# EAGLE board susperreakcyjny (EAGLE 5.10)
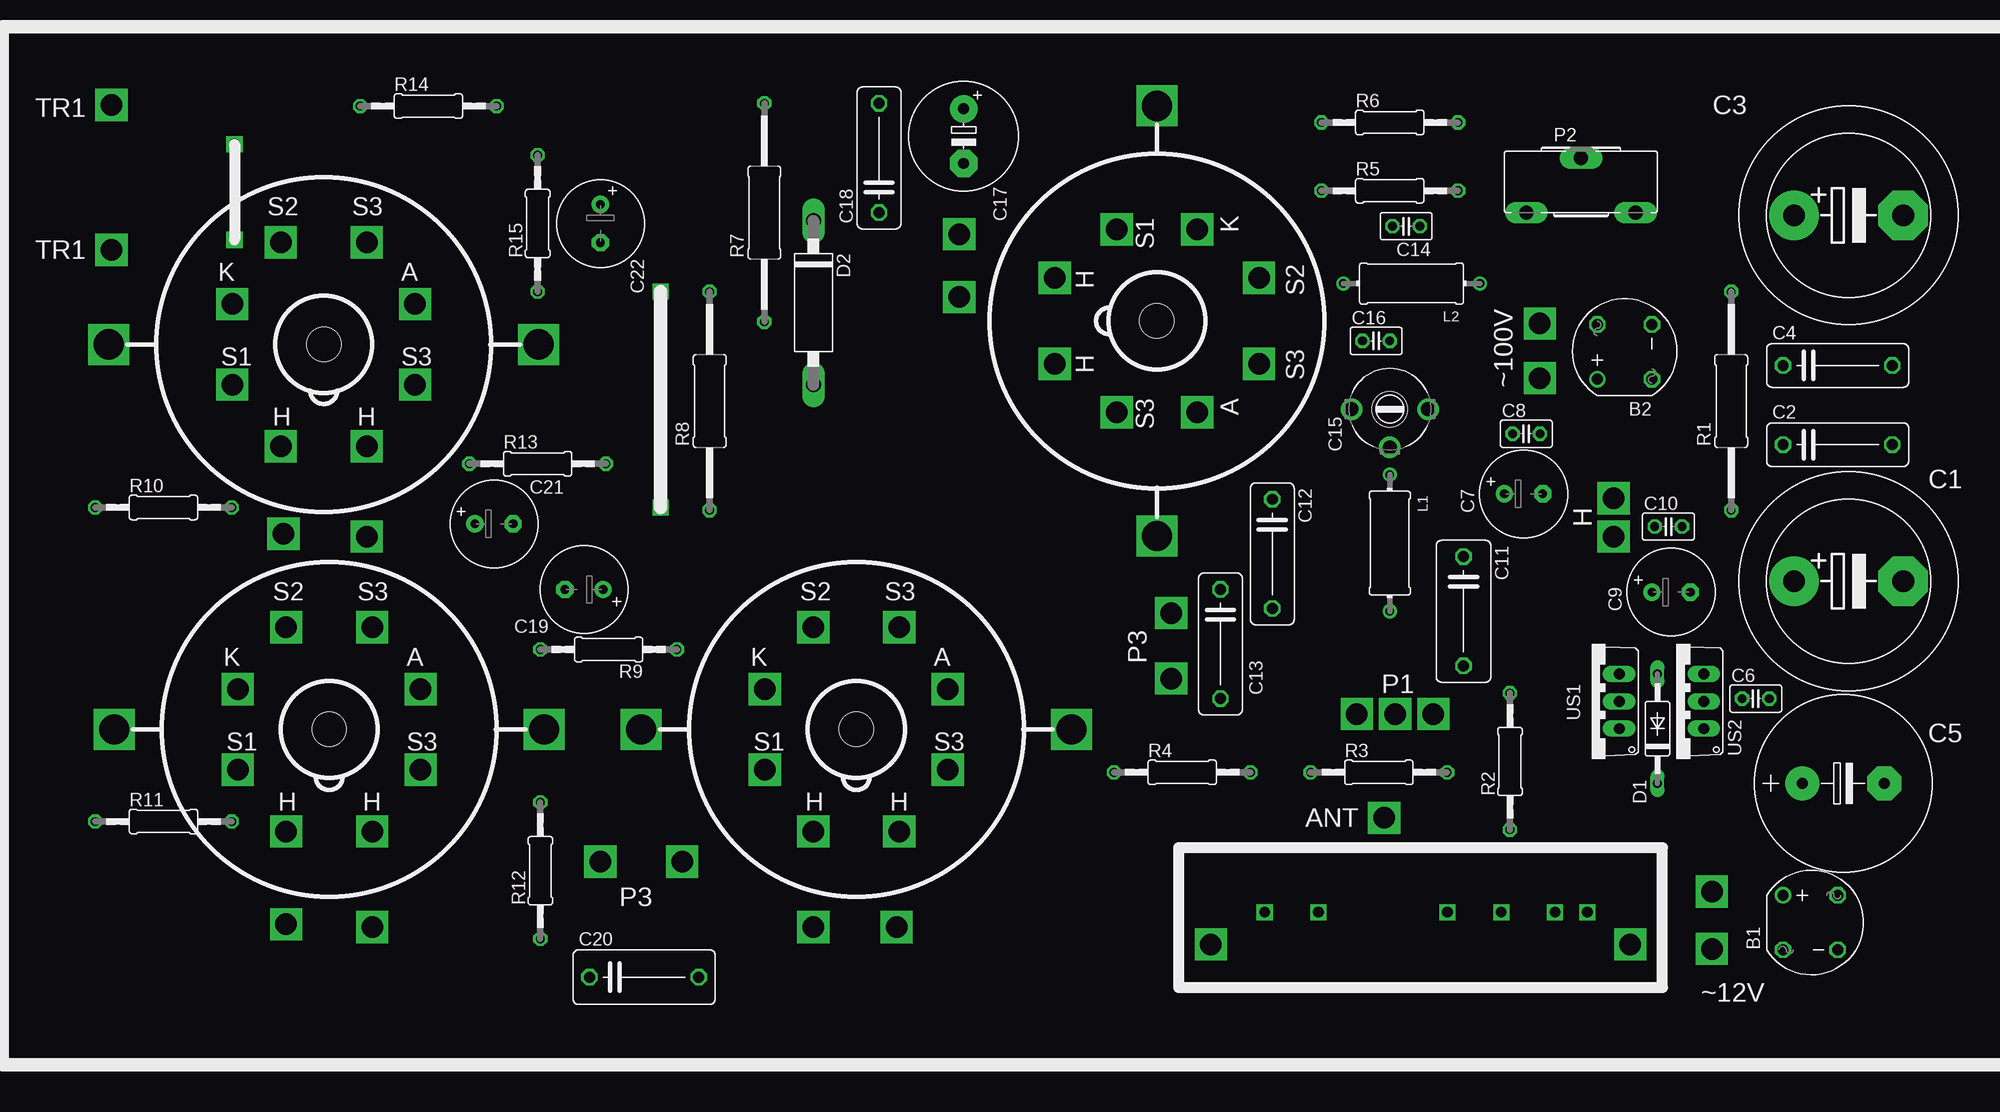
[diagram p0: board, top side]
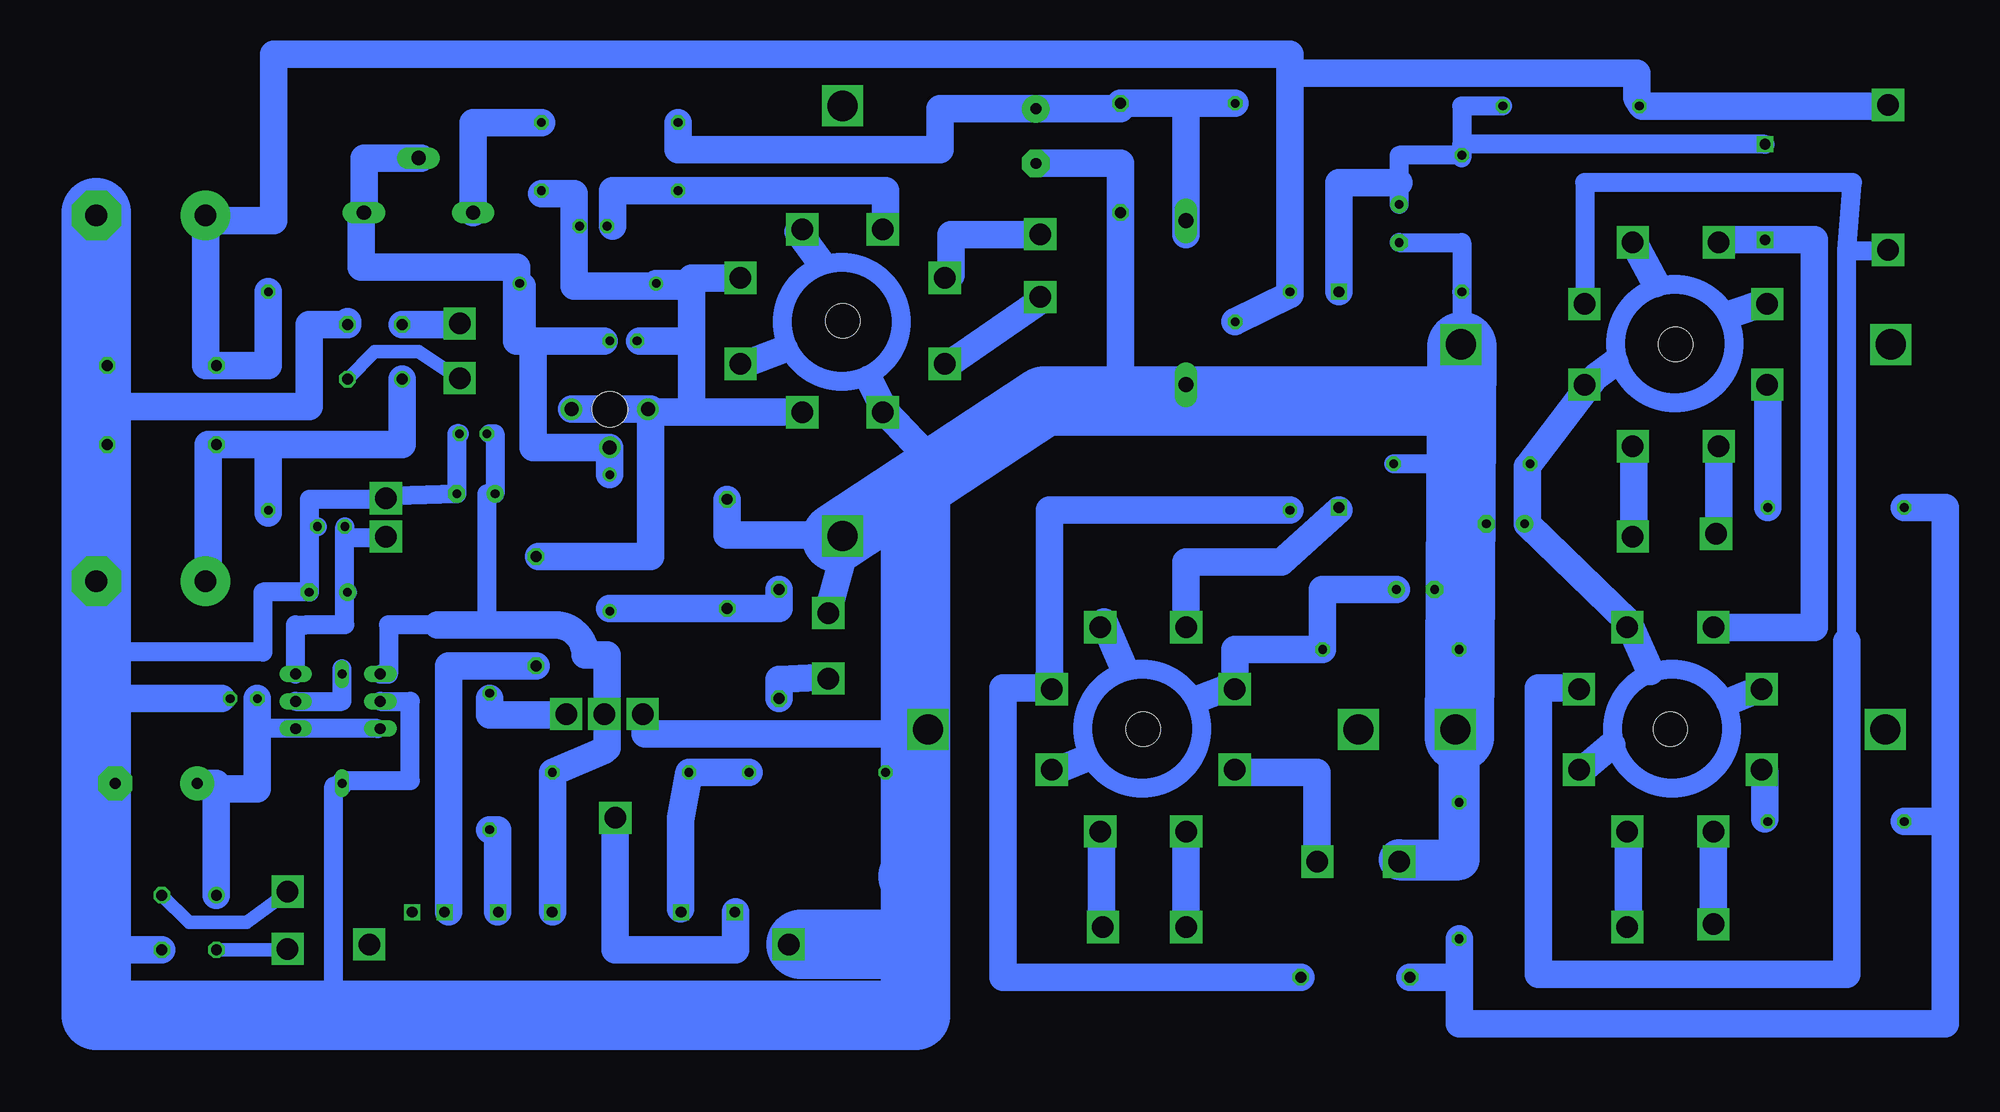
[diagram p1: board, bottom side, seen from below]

No outline drawn. Coordinates in mm, seen from the top.
Copper layers (1*16): Top 0.035mm / dielectric 1.5mm / Bottom 0.035mm
Design rules "default": minimum track width 10mil, minimum drill 24mil, track to track 8mil, track to pad 8mil, pad to pad 8mil, via to via 8mil, smd to smd 8mil, copper to edge 40mil, drill to drill 8mil, minimum pad ring 10mil, minimum via ring 8mil, stop-mask expansion 4mil, vias tented up to drill 0mil, thermal gap 10mil
Holes 3.2 mm at 30.4,30.92 107.37,68.92 29.89,66.73 79.42,30.92

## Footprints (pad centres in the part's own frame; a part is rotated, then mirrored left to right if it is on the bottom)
RB1A = drill 1.016 round: + -2.54,2.54 | drill 1.016 octagon: - 2.54,-2.54; AC1 2.54,2.54; AC2 -2.54,-2.54
EB20D = drill 2.007 pad 4.597 round: + -5.08,0 | drill 2.007 pad 4.597 octagon: - 5.08,0
C102-043X133 = drill 1.016 octagon: 1 -5.08,0; 2 5.08,0
E7,5-16 = drill 1.016 pad 3.15 round: + -3.81,0 | drill 1.016 pad 3.15 octagon: - 3.81,0
C025-025X050 = drill 0.813 octagon: 1 -1.27,0; 2 1.27,0
E3,5-8 = drill 0.813 pad 1.6 round: + -1.778,0 | drill 0.813 pad 1.6 octagon: - 1.778,0
C102-054X133 = drill 1.016 octagon: 1 -5.08,0; 2 5.08,0
CTRIM808-1 = drill 1.321 round: 1 -3.556,0; 2 0,-3.556; 3 3.556,0 | hole 3.302: 0,0
E5-10,5 = drill 1.016 pad 2.54 round: + -2.54,0 | drill 1.016 pad 2.54 octagon: - 2.54,0
C2992 = drill 0.813 long: A 5.08,0; C -5.08,0
C1702-15 = drill 1.397 long: A 7.62,0; C -7.62,0
LAL04 = drill 0.8 pad 1.3 round: 1 -6.35,0; 2 6.35,0
CA14H = drill 1.321 long: A -5.08,0; E 5.08,0; S 0,5.08
0309/20 = drill 0.813 octagon: 1 -10.16,0; 2 10.16,0
0207/12 = drill 0.813 octagon: 1 -6.35,0; 2 6.35,0
TO220V = drill 1.016 long: 1 -2.54,-2.54; 2 0,-2.54; 3 2.54,-2.54

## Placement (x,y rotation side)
B1  [RB1A]  168.15,12.95 0 top
B2  [RB1A]  150.88,66.04 90 top
C1  [EB20D]  171.7,44.7 0 top
C2  [C102-043X133]  170.69,57.4 0 top
C3  [EB20D]  171.7,78.74 0 top
C4  [C102-043X133]  170.69,64.77 0 top
C5  [E7,5-16]  171.2,25.91 0 top
C6  [C025-025X050]  163.07,33.78 0 top
C7  [E3,5-8]  141.48,52.83 0 top
C8  [C025-025X050]  141.73,58.42 0 top
C9  [E3,5-8]  155.19,43.69 0 top
C10  [C025-025X050]  154.94,49.78 0 top
C11  [C102-054X133]  135.89,41.91 270 top
C12  [C102-043X133]  118.11,47.24 270 top
C13  [C102-043X133]  113.28,38.86 270 top
C14  [C025-025X050]  130.56,77.72 180 top
C15  [CTRIM808-1]  129.03,60.71 0 top
C16  [C025-025X050]  127.76,67.06 0 top
C17  [E5-10,5]  89.41,86.11 270 top
C18  [C102-043X133]  81.53,84.07 90 top
C19  [E3,5-8]  54.1,43.94 180 top
C20  [C102-054X133]  59.69,7.87 0 top
C21  [E3,5-8]  45.72,50.04 0 top
C22  [E3,5-8]  55.63,77.98 270 top
D1  [C2992]  153.92,30.99 90 top
D2  [C1702-15]  75.44,70.61 270 top
L1  [LAL04]  129.03,48.26 270 top
L2  [LAL04]  131.06,72.39 180 top
P2  [CA14H]  146.81,78.99 0 top
R1  [0309/20]  160.78,61.47 90 top
R2  [0207/12]  140.21,27.94 90 top
R3  [0207/12]  128.02,26.92 0 top
R4  [0207/12]  109.73,26.92 0 top
R5  [0207/12]  129.03,81.03 0 top
R6  [0207/12]  129.03,87.38 0 top
R7  [0309/20]  70.87,78.99 90 top
R8  [0309/20]  65.79,61.47 90 top
R9  [0207/12]  56.39,38.35 180 top
R10  [0207/12]  14.99,51.56 0 top
R11  [0207/12]  14.99,22.35 0 top
R12  [0207/12]  50.04,17.78 90 top
R13  [0207/12]  49.78,55.63 0 top
R14  [0207/12]  39.62,88.9 0 top
R15  [0207/12]  49.78,77.98 90 top
US1  [TO220V]  147.83,33.53 90 top
US2  [TO220V]  155.7,33.53 90 top

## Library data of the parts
B1 B2 = rectifier
C1-C22 L1 L2 R1-R15 = rcl
D1 D2 = diode
P2 = pot
US1 US2 = transistor-npn

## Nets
S$37: C22.- R15.1
S$40: R10.2
S$41: C20.1 R10.1 R11.1 R12.1
S$43: R13.2
S$46: C22.+ R14.2
S$47: R12.2
S$62: C19.+ R9.1
S$63: C20.2 R8.1
S$69: C17.+ C18.2 R7.2
S$72: L2.2
S$74: P2.E
S$75: C17.-
S$76: C15.2 L1.1
S$77: C12.2
S$80: C13.2
S$81: C15.3
S$92: C11.2
S$94: R3.1 R4.2
S$95: R3.2
S$97: R2.1
S$99: C9.- C10.2
S$100: C13.1
S$101: B2.AC2
S$102: R1.2 R7.1
S$104: B2.+ C2.1
S$105: B2.AC1
S$106: D1.A
S$108: B1.AC1
S$109: B1.-
S$110: B1.+ C5.+
S$112: C6.1
S$114: US1.3
S$115: P2.A R6.2
S$116: C7.- C8.2
S$117: C7.+
S$119: US2.2
S$120: US1.2
S$121: C9.+ C10.1 US2.3
S$122: R6.1
S$129: C12.1

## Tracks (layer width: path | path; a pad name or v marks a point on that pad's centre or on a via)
S$1  (via drill 2)
  other vias: 34.4,40.41
S$2  (via drill 2)
  other vias: 26.4,40.41
S$3  (via drill 2)
  other vias: 21.9,34.67
S$4  (via drill 2)
  other vias: 38.9,34.67
S$5  (via drill 2)
  other vias: 38.9,27.17
S$6  (via drill 2)
  other vias: 21.9,27.17
S$7  (via drill 2)
  other vias: 26.4,21.43 26.4,12.79 10.14,75.53 10.14,88.99
S$8  (via drill 2)
  other vias: 34.4,21.43 34.4,12.54
S$9  (via drill 2.8)
  other vias: 50.4,30.92
S$10  (via drill 2.8)
  other vias: 10.4,30.92
S$11  (via drill 2)
  other vias: 116.87,72.92
S$12  (via drill 2)
  other vias: 116.87,64.92
S$13  (via drill 2)
  other vias: 111.12,77.42
S$14  (via drill 2)
  other vias: 111.12,60.42
S$15  (via drill 2)
  other vias: 103.63,60.42
S$16  (via drill 2)
  other vias: 103.63,77.42
S$17  (via drill 2)
  other vias: 97.88,72.92 88.99,76.98 88.99,71.14
S$18  (via drill 2)
  other vias: 97.88,64.92
S$19  (via drill 2.8)
  other vias: 107.37,48.92
S$20  (via drill 2.8)
  other vias: 107.37,88.92
S$21  (via drill 2)
  other vias: 25.89,76.23
S$22  (via drill 2)
  other vias: 33.89,76.23
S$23  (via drill 2)
  other vias: 21.39,70.48
S$24  (via drill 2)
  other vias: 38.39,70.48
S$25  (via drill 2)
  other vias: 38.39,62.99
S$26  (via drill 2)
  other vias: 21.39,62.99
S$27  (via drill 2)
  other vias: 25.89,57.24 26.14,49.11
S$28  (via drill 2)
  other vias: 33.89,57.24 33.89,48.86
S$29  (via drill 2.8)
  other vias: 49.89,66.73
S$30  (via drill 2.8)
  other vias: 9.89,66.73
S$31
  Bottom 2.54: 37.34,63.75 35.56,65.02 | 37.34,63.75 38.35,62.74 | 37.34,63.75 43.69,55.37 43.69,50.04 34.29,40.89 32.26,36.32
S$32
  Bottom 2.54: 26.42,21.08 26.42,12.95
S$33
  Bottom 2.54: 34.29,20.83 34.29,12.45
S$34
  Bottom 2.54: 88.9,76.96 97.28,76.96 97.28,73.15
S$35
  Bottom 2.54: 25.91,56.39 25.91,49.02
S$36
  Bottom 2.54: 33.78,56.64 33.78,48.77
S$37
  Bottom 1.778: 49.78,66.55 R15.1 49.78,76.2 C22.-
  Bottom 6.452: 49.78,66.55 50.04,30.23
S$38  (via drill 1)
  Bottom 2.54: 25.91,76.45 v21.59,76.45 17.02,76.45 17.02,40.39 26.42,40.39
S$39
  Bottom 2.54: 21.59,22.61 21.59,26.92
S$40
  Bottom 2.54: R10.2 21.34,62.74
S$41
  Bottom 2.54: R10.1 4.83,51.56 4.83,22.35 | 4.83,22.35 R11.1 | 4.83,22.35 4.83,3.56 50.04,3.56 50.04,7.87 | R12.1 50.04,7.87 | C20.1 50.04,7.87
S$42
  Bottom 1.778: 38.35,70.61 38.35,81.79 13.46,81.79 13.97,75.44 | 13.97,75.44 10.16,75.44 | 13.97,39.62 13.97,75.44
S$43
  Bottom 1.778: R13.2 51.82,55.63 51.82,55.37
S$44
  Bottom 2.54: 174.5,60.96 156.97,60.96 156.97,68.58 153.42,68.58 153.42,68.83
S$45
  Bottom 2.54: 88.9,70.87 97.28,65.02
S$46  (via drill 1)
  Bottom 1.778: R14.2 49.78,88.9 49.78,85.34 | 49.78,84.33 49.78,84.07 | 49.78,84.33 55.63,84.33 55.63,81.79 C22.+ | v21.59,85.34 49.78,85.34 | 49.78,85.34 49.78,84.33
  Bottom 2.54: 55.63,81.79 61.21,81.79 v61.21,71.63
S$47
  Bottom 2.54: R12.2 50.04,28.45
S$48  (via drill 2)
  other vias: 75.42,40.41
S$49  (via drill 2)
  other vias: 83.42,40.41
S$50  (via drill 2)
  other vias: 70.92,34.67
S$51  (via drill 2)
  other vias: 87.92,34.67
S$52  (via drill 2)
  other vias: 87.92,27.17
S$53  (via drill 2)
  other vias: 70.92,27.17
S$54  (via drill 2)
  other vias: 75.42,21.43 75.42,12.54 63.23,18.63 55.61,18.63 108.69,35.65 108.69,41.75 128.51,22.7 133.08,32.35 129.52,32.35 125.97,32.35 142.98,68.67 142.98,63.59 158.99,10.51 158.99,15.84 149.84,52.42 149.84,48.86
S$55  (via drill 2)
  other vias: 83.42,21.43 83.17,12.54
S$56  (via drill 2.8)
  other vias: 99.42,30.92
S$57  (via drill 2.8)
  other vias: 59.42,30.92
S$58
  Bottom 3.81: 55.63,18.8 50.04,18.8 50.04,30.73
S$59
  Bottom 2.54: 87.88,26.92 84.84,28.19
S$60
  Bottom 2.54: 75.44,20.83 75.44,12.7
S$61
  Bottom 2.54: 83.31,20.83 83.31,12.7
S$62
  Bottom 2.54: C19.+ 62.74,43.94 R9.1 70.87,38.35 70.87,35.05 74.17,33.78
S$63
  Bottom 2.54: 87.88,34.8 88.14,34.8 | 88.14,34.8 92.46,34.8 92.46,7.87 C20.2 | R8.1 88.14,51.31 88.14,34.8
S$64  (via drill 1)
  other vias: 61.21,51.56
S$65
  Bottom 2.54: 99.06,55.88 103.38,60.45 104.9,63.5
S$66
  Bottom 2.54: 61.21,51.31 66.55,46.48 75.44,46.48 75.44,40.89
S$67
  Bottom 6.452: 50.04,61.47 88.65,61.47 107.95,48.77
S$68
  Bottom 2.54: 103.38,77.72 103.38,81.03 128.78,81.03 128.78,77.72
S$69
  Bottom 2.54: 98.3,84.84 98.3,88.65 C17.+ 81.53,88.65 C18.2 75.44,89.15 | 75.44,89.15 R7.2 | 75.44,76.96 75.44,89.15
S$70
  Bottom 2.54: 70.87,26.92 63.25,26.92 63.25,18.54
S$71
  Bottom 2.54: 126.24,67.06 121.67,67.06
S$72
  Bottom 2.54: 135.38,80.77 132.33,80.77 132.33,72.14 121.41,72.14 | 111.51,60.45 121.41,60.45 | 121.41,60.45 121.41,72.14 | 121.41,72.14 121.41,72.39 | 121.41,72.39 121.41,72.9 117.35,72.9 | L2.2 121.41,72.39 | 125.48,60.45 121.41,60.45
S$74
  Bottom 2.54: 146.56,84.07 151.89,84.07 P2.E 152.15,78.99 152.15,73.91 137.67,73.91 137.67,67.06
S$75
  Bottom 2.54: C17.- 81.53,83.57 81.53,62.74
S$76
  Bottom 2.54: L1.1 C15.2 136.14,57.15 136.14,66.8 136.14,67.06 | 137.16,72.14 137.16,67.06 136.14,67.06 | 129.54,67.06 136.14,67.06
S$77
  Bottom 2.54: 129.03,42.16 C12.2 113.28,42.16
S$78
  Bottom 6.452: 111.25,10.92 100.58,10.92 100.58,53.34
S$79
  Bottom 2.54: 108.71,41.91 106.68,49.28
S$80
  Bottom 2.54: 108.71,35.81 113.28,35.56 C13.2
S$81
  Bottom 2.54: 135.64,46.99 125.22,46.99 125.22,60.71 C15.3
S$82  (via drill 2)
  other vias: 112.4,10.92
S$83  (via drill 2)
  other vias: 151.4,10.92
S$84  (via drill 1)
  other vias: 147.4,13.92
S$85  (via drill 1)
  other vias: 144.4,13.92
S$86  (via drill 1)
  other vias: 139.4,13.92
S$87  (via drill 1)
  other vias: 134.4,13.92
S$88  (via drill 1)
  other vias: 122.4,13.92
S$89  (via drill 1)
  other vias: 117.4,13.92
S$90
  Bottom 3.81: 112.27,10.92 101.6,10.92 101.6,52.07
S$91
  Bottom 2.54: 117.35,13.97 117.35,10.41 128.52,10.41 128.52,22.61
S$92
  Bottom 2.54: 144.02,13.97 144.02,36.83 C11.2
S$93
  Bottom 6.452: 100.84,17.27 100.58,17.27 100.58,4.32 176.78,4.32 176.78,78.99
S$94
  Bottom 2.54: 122.43,14.22 122.43,22.61 R3.1 R4.2
S$95
  Bottom 2.54: 134.37,13.97 R3.2 129.54,28.96
S$96
  Bottom 2.54: 125.73,32.51 125.73,30.48 102.11,30.48
S$97
  Bottom 2.54: 139.45,13.97 139.45,21.59 R2.1
S$98
  Bottom 2.54: 140.21,33.78 140.21,32.26 133.35,32.26
S$99
  Bottom 1.778: C10.2 156.97,49.78 | 156.97,49.78 156.97,45.47 C9.- 161.29,43.69 161.29,38.1 175.01,38.1 | 150.11,52.32 156.97,52.32 156.97,49.78
S$100
  Bottom 2.54: C13.1 113.28,42.42
S$101
  Bottom 1.27: B2.AC2 150.88,66.04 146.81,66.04 143,63.5
S$102
  Bottom 1.778: 33.02,88.9 33.27,89.66
  Bottom 2.54: R1.2 160.78,64.77 166.62,64.77 166.62,78.23 160.27,78.23 160.27,93.73 65.79,93.73 65.79,91.95 | 10.16,88.9 33.02,88.9 33.53,89.66 33.53,91.95 65.79,91.95 | 65.79,91.95 65.79,71.37 R7.1
S$103
  Bottom 2.54: 174.75,60.45 174.75,60.71
S$104
  Bottom 2.54: B2.+ 148.34,57.4 160.78,57.4 | 166.37,44.7 166.37,57.4 C2.1 160.78,57.4 | 160.78,57.4 160.78,51.05
S$105
  Bottom 2.54: 143,68.58 B2.AC1
S$106
  Bottom 1.778: 153.92,33.78 D1.A
S$107
  Bottom 1.27: 165.35,10.41 159,10.41
S$108
  Bottom 1.27: B1.AC1 168.15,12.95 162.81,12.95 159,15.75
S$109
  Bottom 2.54: B1.- 174.5,10.41
S$110
  Bottom 2.54: B1.+ 165.61,25.91 C5.+
S$111
  Bottom 2.54: 165.1,33.78 174.5,33.78
S$112
  Bottom 2.54: C6.1 161.8,25.4 165.86,25.4
S$113
  Bottom 1.778: 147.57,33.53 147.57,26.16 153.92,26.16 153.92,25.65 154.69,25.65 154.69,4.06
S$114
  Bottom 1.778: 144.27,40.64 149.61,40.64 149.61,36.07 US1.3
  Bottom 2.54: 129.29,29.21 129.29,37.85 131.32,37.85 arc-90 134.11,40.64 144.27,40.64 145.03,40.64
S$115
  Bottom 2.54: R6.2 141.73,87.38 P2.A
S$116
  Bottom 1.778: C8.2 143.26,58.42 C7.- 150.37,52.58
S$117
  Bottom 1.778: 140.21,58.42 139.7,58.42 C7.+ 140.46,52.83 140.46,40.39
S$118
  Bottom 1.778: 150.62,30.99 161.54,30.99
S$119
  Bottom 1.778: US2.2 153.92,33.53 153.92,36.58
S$120
  Bottom 1.778: US1.2 147.57,33.53
S$121
  Bottom 1.778: US2.3 158.24,40.64 157.23,40.64 155.7,40.64 153.67,40.64 153.67,43.94 | 153.67,48.77 C10.1 | 153.67,48.77 149.86,48.77 | 153.67,43.94 153.67,48.77 | 153.67,43.94 C9.+
S$122
  Bottom 2.54: 98.3,84.84 122.68,84.84 R6.1
S$123
  Bottom 2.54: 21.59,70.61 24.64,69.6
S$124
  Bottom 2.54: 33.78,76.2 31.75,72.39
S$125
  Bottom 2.54: 38.86,26.92 35.81,29.46
S$126
  Bottom 2.54: 13.97,39.12 13.97,8.13 42.67,8.13 42.67,21.34 42.67,24.13 42.67,34.8 38.86,34.8
S$127
  Bottom 2.54: 21.84,34.8 24.89,33.53
S$128
  Bottom 2.54: 83.06,40.89 81.28,36.83
S$129
  Bottom 2.54: C12.1 118.11,49.02 107.44,49.02
S$130
  Bottom 2.54: 111.51,77.22 109.47,74.42
S$131
  Bottom 2.54: 116.84,64.77 112.78,66.29
(copper drawn outside any net)
  shapes: Bottom circle x4

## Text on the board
tNames: TR1 | S2 | S3 | K | S1 | TR1 | H | S2 | K | A | H | S3 | S1 | S3 | ~100V | S3 | A | H | H | H | S2 | S3 | S2 | S3 | K | A | K | A | P3 | P1 | S1 | S3 | S1 | S3 | H | H | H | H | ANT | P3 | ~12V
